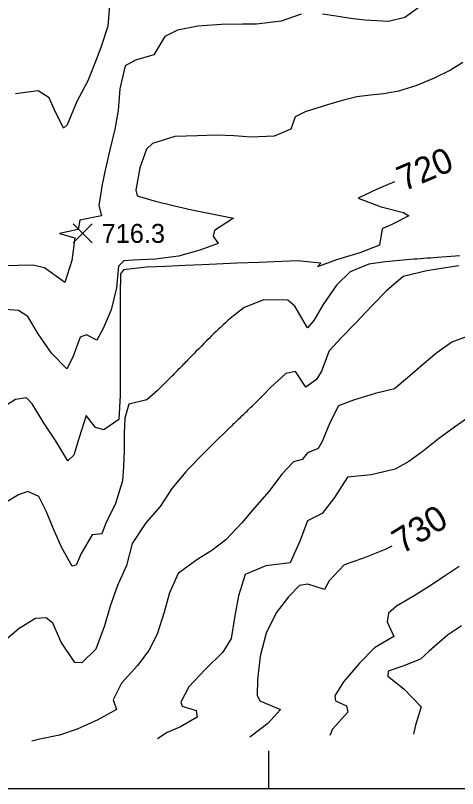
# Model space of a CAD drawing. Extents: x 2566079 to 2571326, y 424054 to 426896.
# Drawn here: x 2567799 to 2568149, y 424077 to 424690 of the extents above; entities that cross this region are included whole.
import ezdxf

# ---------------------------------------------------------------- set-up
doc = ezdxf.new("R2010")
doc.units = 0
for name, color, linetype in [('Contour_ADS_Label_Major', 7, 'Continuous'), ('Contour_ADS_Major', 7, 'Continuous'), ('Contour_ADS_Minor', 7, 'Continuous'), ('Contour_ADS_Spot_Elevation', 7, 'Continuous'), ('Contour_ADS_State_Plane_Border', 7, 'Continuous')]:
    doc.layers.add(name, color=color, linetype=linetype)

# ---------------------------------------------------------------- blocks, each defined once
blk = doc.blocks.new('S750')
at = {"layer": 'Contour_ADS_Spot_Elevation'}
for p, q in [((-0.5, 0.498), (0.5, -0.498)), ((-0.498, -0.5), (0.498, 0.5))]:
    blk.add_line(p, q, dxfattribs=at)

msp = doc.modelspace()

# ---------------------------------------------------------------- linework, layer by layer
at = {"layer": 'Contour_ADS_Major'}
for points in [[(2568099.6, 424558.25), (2568085.65, 424552.28), (2568070.71, 424545.24), (2568088.93, 424538.4), (2568106.68, 424533.78), (2568110.87, 424531.28), (2568097.47, 424524.46), (2568089.67, 424521), (2568087.56, 424507.99), (2568071.96, 424501.96), (2568053.61, 424496.3), (2568038.43, 424490.77), (2568041.01, 424493.82), (2568022.58, 424495.56), (2568010.26, 424494.94), (2567992.35, 424494.36), (2567974.49, 424493.82), (2567958.44, 424492.93), (2567947.2, 424492.34), (2567933.64, 424491.76), (2567918.12, 424491.21), (2567903.03, 424490.6), (2567884.74, 424488.47), (2567882.34, 424485.39), (2567881.98, 424468.69), (2567881.96, 424454.64), (2567881.96, 424437.97), (2567881.97, 424419.92), (2567881.99, 424402.74), (2567882.01, 424388.95), (2567881.09, 424369.71), (2567869.26, 424361.61), (2567862.62, 424363.51), (2567855.27, 424373.01), (2567849.47, 424355.43), (2567845.26, 424341.35), (2567840.65, 424337.08), (2567830.82, 424353), (2567821.96, 424366.64), (2567812.34, 424382.26), (2567807.79, 424386.89), (2567799.12, 424385.54), (2567783.17, 424375.78)], [(2568097.28, 424269.19), (2568092.12, 424266.58), (2568075.05, 424259.82), (2568059.64, 424254.5), (2568047.76, 424241.73), (2568044.04, 424234.86), (2568030.9, 424239.23), (2568024.21, 424238.23), (2568015.44, 424229.01), (2568005.84, 424216.33), (2567997.68, 424200.31), (2567993.11, 424182.09), (2567991.05, 424163.19), (2567990.58, 424151.14), (2567992.71, 424146.72), (2568009.09, 424139.76), (2567999.17, 424128.74), (2567985.78, 424118.53), (2567984.74, 424117.91)]]:
    msp.add_lwpolyline(points, dxfattribs=at)
at = {"layer": 'Contour_ADS_Minor'}
for p, q in [((2567817.09, 424630.46), (2567799.12, 424627.92)), ((2567801.27, 424491.98), (2567781.86, 424491.58))]:
    msp.add_line(p, q, dxfattribs=at)
for points in [[(2567873.71, 424698.35), (2567872.31, 424681.74), (2567867.06, 424665.48), (2567863.62, 424656.22), (2567856.34, 424638.44), (2567847.67, 424621.82), (2567839.97, 424603.52), (2567837.22, 424600.72), (2567829.87, 424615.81), (2567825.93, 424624.81), (2567817.09, 424630.46)], [(2568121.69, 424698.47), (2568107.56, 424688.48), (2568094.69, 424685.41), (2568075.94, 424686.43), (2568064.62, 424687.83), (2568053.16, 424689.6), (2568042.34, 424691.16)], [(2568025.51, 424691.14), (2568009.73, 424685.6), (2567990, 424683.22), (2567979.06, 424683.35), (2567962.39, 424683.03), (2567943.6, 424681.63), (2567927.45, 424678.51), (2567917.53, 424673.39), (2567908.78, 424658.94), (2567894.23, 424654.81), (2567886.13, 424650.1), (2567881.71, 424632), (2567880.48, 424614.79), (2567877.96, 424600.08), (2567873.84, 424583.54), (2567870.25, 424567.59), (2567867.75, 424556.13), (2567865.12, 424539.48), (2567867.34, 424531.3), (2567850.09, 424527.88), (2567848.83, 424520.3), (2567834.04, 424517.33), (2567846.15, 424513.94), (2567843.9, 424495.86), (2567838.25, 424478.43), (2567822.25, 424490.14), (2567812.95, 424492.17), (2567801.27, 424491.98)], [(2568153.66, 424652.92), (2568143.78, 424646.86), (2568130.86, 424640.36), (2568116.49, 424634.42), (2568102.69, 424630.08), (2568090.92, 424627.95), (2568080.4, 424626.96), (2568069.75, 424625.61), (2568058.08, 424622.83), (2568046.42, 424619.27), (2568028.75, 424613.74), (2568020.71, 424609.66), (2568017.33, 424599.99), (2568004.15, 424594.33), (2567985.63, 424593.74), (2567972.33, 424594.77), (2567958.24, 424595.13), (2567943.28, 424594.69), (2567925.46, 424594.18), (2567907.84, 424588.55), (2567902.91, 424584.2), (2567897.65, 424569.36), (2567894.62, 424551.62), (2567895.46, 424547.18), (2567909.13, 424543.13), (2567925.19, 424539.14), (2567938.82, 424535.93), (2567954.61, 424532.92), (2567971.85, 424529.31), (2567956.9, 424519.59), (2567955.9, 424515.27), (2567959.62, 424509.21), (2567945.15, 424503.91), (2567928.23, 424499.35), (2567910.21, 424496.93), (2567892.4, 424496.02), (2567884.97, 424495.51), (2567880.75, 424491.45), (2567879.26, 424474.15), (2567875.01, 424456.71), (2567868.66, 424441.9), (2567863.58, 424432.73), (2567855.35, 424436.84), (2567850.5, 424434.96), (2567844.53, 424419.24), (2567839.93, 424409.84), (2567827.59, 424422.28), (2567817.13, 424437.64), (2567808.96, 424451.45), (2567801.62, 424456.11), (2567790.93, 424456.95)], [(2568112.01, 424496.58), (2568092.49, 424494.76), (2568079.02, 424492.81), (2568064.33, 424486.79), (2568053.51, 424476.39), (2568042.96, 424460.88), (2568035.58, 424448.22), (2568030.49, 424442.5), (2568020.64, 424459.68), (2568014.92, 424464.28), (2567995.89, 424464.72), (2567980.42, 424458.57), (2567969.32, 424449.91)], [(2568151.31, 424499.51), (2568133.44, 424498.22)], [(2568150.52, 424491.51), (2568138.3, 424489.86), (2568125.1, 424487.78), (2568106.44, 424483.28), (2568093.11, 424471.91), (2568081.69, 424460.05), (2568068.75, 424446.53), (2568057.78, 424435.01), (2568047.72, 424424.23), (2568041.71, 424408.12), (2568037.55, 424401.43), (2568029.11, 424395.37), (2568020.92, 424407.71), (2568013.41, 424406.22), (2568001.03, 424394.88), (2567996.26, 424389.89), (2567986.69, 424380.42)], [(2568163.46, 424438), (2568144.99, 424431.12), (2568133.17, 424422.62), (2568121.4, 424412.83), (2568111.77, 424404.37), (2568099.4, 424394.2), (2568084.14, 424390.4), (2568066.93, 424385.09), (2568055.04, 424380.63), (2568048.24, 424367.01), (2568042.22, 424352.28), (2568038.9, 424346.88), (2568030.46, 424343.42), (2568026.21, 424337.97), (2568019.51, 424336.29), (2568010.31, 424326.44), (2568000.27, 424312.97), (2567988.47, 424299.83), (2567978.58, 424287.78), (2567965.84, 424274.32), (2567954.78, 424265.85), (2567942.83, 424258.5), (2567928.12, 424247.7), (2567921.12, 424232.26), (2567916.95, 424217), (2567911.32, 424199.42), (2567904.84, 424186.46), (2567895.78, 424174.55), (2567883.03, 424160.54), (2567876.65, 424147.36), (2567879.09, 424139.66), (2567864.41, 424131.64), (2567848.02, 424124.25), (2567834.12, 424119.43), (2567818.33, 424116.23), (2567812.13, 424114.77)], [(2567923.33, 424404.29), (2567911.74, 424392.69), (2567903.29, 424385.29), (2567888.97, 424381.84), (2567885.72, 424370.87), (2567885.35, 424358.78), (2567885.18, 424345.18), (2567884.81, 424332.23), (2567884.01, 424320.99), (2567878.17, 424302.29), (2567871.09, 424288.43), (2567867.62, 424279.18), (2567860.03, 424278.18), (2567851.26, 424263.52), (2567847.25, 424254.37), (2567844.09, 424253.48), (2567835.91, 424267.87), (2567829.79, 424281.79), (2567823.44, 424296.94), (2567817.53, 424308.81), (2567808.96, 424312.63), (2567801.4, 424309.97), (2567789.64, 424302.98)], [(2568158.45, 424371.71), (2568146.92, 424363.66), (2568134.49, 424354.39), (2568122.35, 424344.97), (2568110.83, 424336.56), (2568100.01, 424330.34), (2568081.11, 424325.94), (2568062.32, 424323.95), (2568051.96, 424307.98), (2568042.23, 424295.22), (2568030.51, 424289.37), (2568024.49, 424273.35), (2568016.78, 424256.17), (2567997.51, 424253.61), (2567981.11, 424246.85), (2567975.97, 424229.96), (2567973.06, 424213.94), (2567970.03, 424196.11), (2567963.34, 424185.28), (2567949.35, 424171.4), (2567936.47, 424157.82), (2567930.04, 424145.56), (2567931.21, 424142.48), (2567942.43, 424138.88), (2567943.17, 424133.71), (2567930, 424126)], [(2567934.14, 424328.27), (2567923.01, 424315.15), (2567913.79, 424300.7), (2567902.51, 424287.83), (2567891.64, 424271.45), (2567887.02, 424253.96), (2567879.93, 424238.04), (2567874.13, 424221.71), (2567869.6, 424206.21), (2567862.68, 424187.7), (2567851.84, 424176.73), (2567846.1, 424177.1), (2567835.38, 424193.31), (2567828.6, 424208.15), (2567823.54, 424212.59), (2567814.92, 424211.98), (2567802.05, 424204.06), (2567787.4, 424191.51)], [(2568150.8, 424253.19), (2568138.92, 424245.29), (2568126.41, 424237.02), (2568115.2, 424229.9), (2568100.98, 424221.7), (2568094.75, 424216.1), (2568093.7, 424209.32), (2568098.88, 424197.72), (2568083.51, 424188.78), (2568071.87, 424176.53), (2568059.01, 424161.73), (2568052.2, 424150.51), (2568052.61, 424146.56), (2568061.4, 424142.57), (2568062.61, 424137.8), (2568050.24, 424124.24), (2568048.33, 424119.06)], [(2568152.61, 424206.25), (2568141.59, 424198.81), (2568127.04, 424186.07), (2568120.07, 424179.68), (2568106.09, 424174.11), (2568094.4, 424170.27), (2568094.2, 424166.29), (2568106.81, 424156.07), (2568120.57, 424141.81), (2568116.15, 424127.45), (2568114.65, 424120.27)], [(2567930, 424126), (2567919.39, 424121.56), (2567911.65, 424116.58)]]:
    msp.add_lwpolyline(points, dxfattribs=at)
for centre, radius, start, end in [((2568343.15, 421617.03), 2888.81, 94.16308, 94.58936), ((2568239.29, 424147.61), 405.31, 131.76652, 134.62107), ((2568952.72, 423428.41), 1418.33, 134.72711, 135.65919), ((2569519.7, 422873.93), 2211.38, 135.65167, 135.93036), ((2566871.29, 425435.23), 1472.96, 315.5805, 315.99945), ((2566961.27, 425433.04), 1469.52, 313.81029, 314.2501), ((2570523.28, 421728.87), 3669.43, 133.90679, 134.08304), ((2569589.43, 422693), 2327.18, 134.08139, 134.7435), ((2568408.5, 423885.54), 648.87, 134.80464, 136.9754)]:
    msp.add_arc(centre, radius, start, end, dxfattribs=at)
at = {"layer": 'Contour_ADS_State_Plane_Border'}
msp.add_line((2568000, 424077.11), (2568000, 424107.11), dxfattribs=at)
msp.add_lwpolyline([(2566079.33, 424077.11), (2571302.93, 424077.11), (2571302.93, 426873.74), (2566079.33, 426873.74), (2566079.33, 424077.11)], close=True, dxfattribs=at)

# ---------------------------------------------------------------- block references
at = {"layer": 'Contour_ADS_Spot_Elevation', "xscale": 15, "yscale": 15}
msp.add_blockref('S750', (2567852.41, 424517.33), dxfattribs=at)

# ---------------------------------------------------------------- texts
at = {"layer": 'Contour_ADS_Label_Major'}
for s, height, rotation, p in [('720', 19.999, 23.12353, (2568106.85, 424550.48)), ('730', 20, 31.8212, (2568105.61, 424262.59))]:
    msp.add_text(s, height=height, rotation=rotation, dxfattribs=at).set_placement(p)
at = {"layer": 'Contour_ADS_Spot_Elevation'}
msp.add_text('716.3', height=15, dxfattribs=at).set_placement((2567867.41, 424509.83))

doc.saveas('drawing.dxf')
